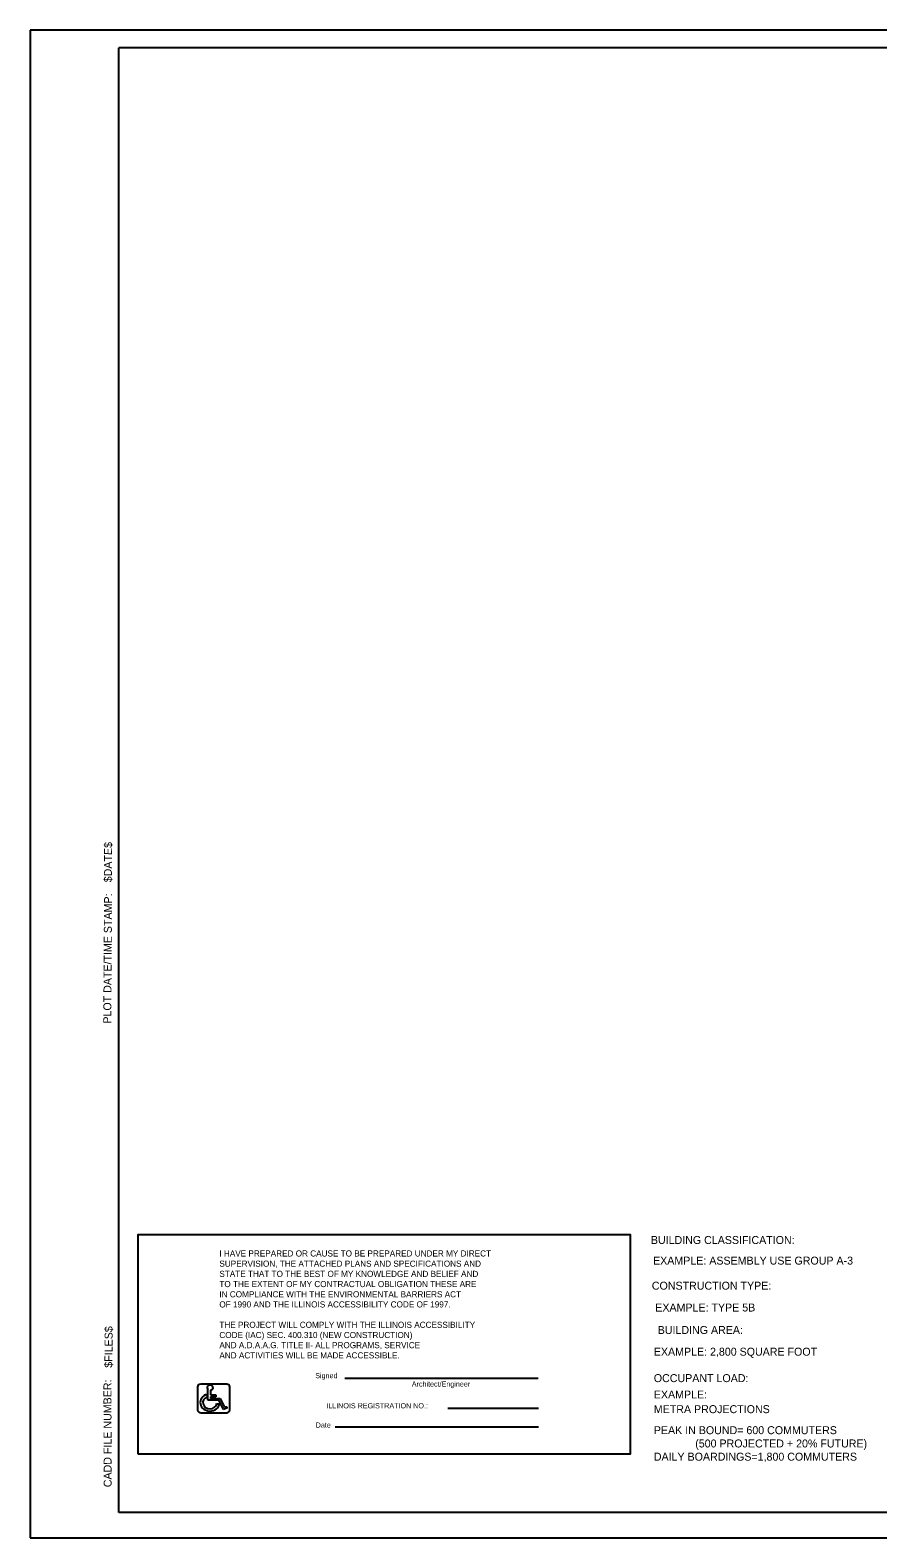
# Model space of a CAD drawing. Extents: x 46.6 to 90.4, y 0.3 to 22.3.
# Drawn here: x 46.58 to 58.96, y 0.26 to 22.28 of the extents above; entities that cross this region are included whole.
import ezdxf

# ---------------------------------------------------------------- set-up
doc = ezdxf.new("R2010")
doc.units = 0
for name, color, linetype in [('A-Patt', 7, 'Continuous'), ('A-Symb', 7, 'Continuous'), ('Level 1', 7, 'Continuous')]:
    doc.layers.add(name, color=color, linetype=linetype)

msp = doc.modelspace()

# ---------------------------------------------------------------- linework, layer by layer
at = {"layer": 'A-Symb'}
for p, q in [((51.179, 2.595), (53.999, 2.595)), ((52.683, 2.155), (54.008, 2.155)), ((51.035, 1.882), (54.008, 1.882))]:
    msp.add_line(p, q, dxfattribs=at)
at = {"layer": 'Level 1'}
for p, q in [((80.605, 22.275), (46.583, 22.275)), ((46.583, 22.275), (46.583, 0.261)), ((47.876, 0.629), (47.876, 22.019)), ((80.019, 22.019), (47.876, 22.019)), ((49.166, 2.356), (49.166, 2.32)), ((49.311, 2.22), (49.349, 2.22)), ((49.406, 2.137), (49.34, 2.271)), ((49.349, 2.22), (49.349, 2.22)), ((49.456, 2.157), (49.406, 2.137)), ((80.019, 0.629), (47.876, 0.629)), ((46.583, 0.261), (80.605, 0.261))]:
    msp.add_line(p, q, dxfattribs=at)
msp.add_lwpolyline([(48.154, 1.486), (55.349, 1.486), (55.349, 4.684), (48.154, 4.684)], close=True, dxfattribs=at)
for points in [[(49.029, 2.464), (49.029, 2.129)], [(49.453, 2.506), (49.076, 2.506)], [(49.18, 2.271), (49.18, 2.428)], [(49.5, 2.129), (49.5, 2.464)], [(49.34, 2.271), (49.18, 2.271)], [(49.218, 2.416), (49.218, 2.347)], [(49.218, 2.347), (49.293, 2.347)], [(49.293, 2.322), (49.218, 2.322)], [(49.218, 2.322), (49.218, 2.296)], [(49.218, 2.296), (49.359, 2.296)], [(49.293, 2.347), (49.293, 2.322)], [(49.359, 2.296), (49.422, 2.166)], [(49.076, 2.087), (49.453, 2.087)]]:
    msp.add_lwpolyline(points, dxfattribs=at)
for centre, major_axis, start_param, end_param in [((49.076, 2.464), (-0.047, 0), 4.712389, 6.283185), ((49.211, 2.454), (0.0423, 0), 4.864081, 10.165802), ((49.453, 2.464), (-0.047, 0), 3.141593, 4.712389), ((49.209, 2.237), (0.141, 0), 1.881085, 6.150799), ((49.209, 2.237), (0.103, 0), 2.000238, 6.102199), ((49.076, 2.129), (0.047, 0), 3.141593, 4.712389), ((49.443, 2.102), (0.0743, 0), 1.400097, 1.856019), ((49.453, 2.129), (0.047, 0), 4.712389, 6.283185), ((49.451, 2.162), (0.00807, 0), 5.359126, 7.164024)]:
    msp.add_ellipse(centre, major_axis=major_axis, ratio=0.890125, start_param=start_param, end_param=end_param, dxfattribs=at)

# ---------------------------------------------------------------- texts
at = {"layer": 'A-Patt'}
for s, height, p in [('Signed', 0.0756, (50.746, 2.592)), ('Architect/Engineer', 0.07556, (52.156, 2.469)), ('ILLINOIS REGISTRATION NO.:', 0.07556, (50.907, 2.152)), ('Date', 0.0756, (50.753, 1.87))]:
    msp.add_text(s, height=height, dxfattribs=at).set_placement(p)
at = {"layer": 'Level 1'}
for s, height, rotation, p in [('$DATE$', 0.1163, 89.6353, (47.776, 9.833)), ('PLOT DATE/TIME STAMP:', 0.11625, 89.6353, (47.767, 7.769)), ('$FILES$', 0.1163, 89.6353, (47.784, 2.745)), ('CADD FILE NUMBER:', 0.11625, 90.1279, (47.773, 1.001))]:
    msp.add_text(s, height=height, rotation=rotation, dxfattribs=at).set_placement(p)
for s, height, p in [('BUILDING CLASSIFICATION:', 0.11625, (55.647, 4.552)), ('I HAVE PREPARED OR CAUSE TO BE PREPARED UNDER MY DIRECT ', 0.08928, (49.346, 4.369)), ('SUPERVISION, THE ATTACHED PLANS AND SPECIFICATIONS AND ', 0.08928, (49.346, 4.22)), ('EXAMPLE: ASSEMBLY USE GROUP A-3', 0.11625, (55.679, 4.251)), ('TO THE EXTENT OF MY CONTRACTUAL OBLIGATION THESE ARE', 0.08928, (49.346, 3.922)), ('STATE THAT TO THE BEST OF MY KNOWLEDGE AND BELIEF AND ', 0.08928, (49.346, 4.071)), ('CONSTRUCTION TYPE:', 0.11625, (55.661, 3.885)), ('IN COMPLIANCE WITH THE ENVIRONMENTAL BARRIERS ACT ', 0.08928, (49.346, 3.773)), ('OF 1990 AND THE ILLINOIS ACCESSIBILITY CODE OF 1997.', 0.08928, (49.346, 3.625)), ('EXAMPLE: TYPE 5B', 0.11625, (55.711, 3.566)), ('THE PROJECT WILL COMPLY WITH THE ILLINOIS ACCESSIBILITY ', 0.08928, (49.346, 3.327)), ('BUILDING AREA:', 0.11625, (55.747, 3.238)), ('AND A.D.A.A.G. TITLE II- ALL PROGRAMS, SERVICE ', 0.08928, (49.346, 3.03)), ('CODE (IAC) SEC. 400.310 (NEW CONSTRUCTION) ', 0.08928, (49.346, 3.178)), ('AND ACTIVITIES WILL BE MADE ACCESSIBLE.', 0.08928, (49.346, 2.881)), ('EXAMPLE: 2,800 SQUARE FOOT', 0.11625, (55.69, 2.921)), ('OCCUPANT LOAD:', 0.11625, (55.69, 2.535)), ('EXAMPLE:', 0.1163, (55.69, 2.296)), ('METRA PROJECTIONS', 0.11625, (55.69, 2.082)), ('PEAK IN BOUND= 600 COMMUTERS', 0.11625, (55.69, 1.775)), ('              (500 PROJECTED + 20% FUTURE)', 0.11625, (55.69, 1.581)), ('DAILY BOARDINGS=1,800 COMMUTERS', 0.11625, (55.69, 1.388))]:
    msp.add_text(s, height=height, dxfattribs=at).set_placement(p)

doc.saveas('drawing.dxf')
